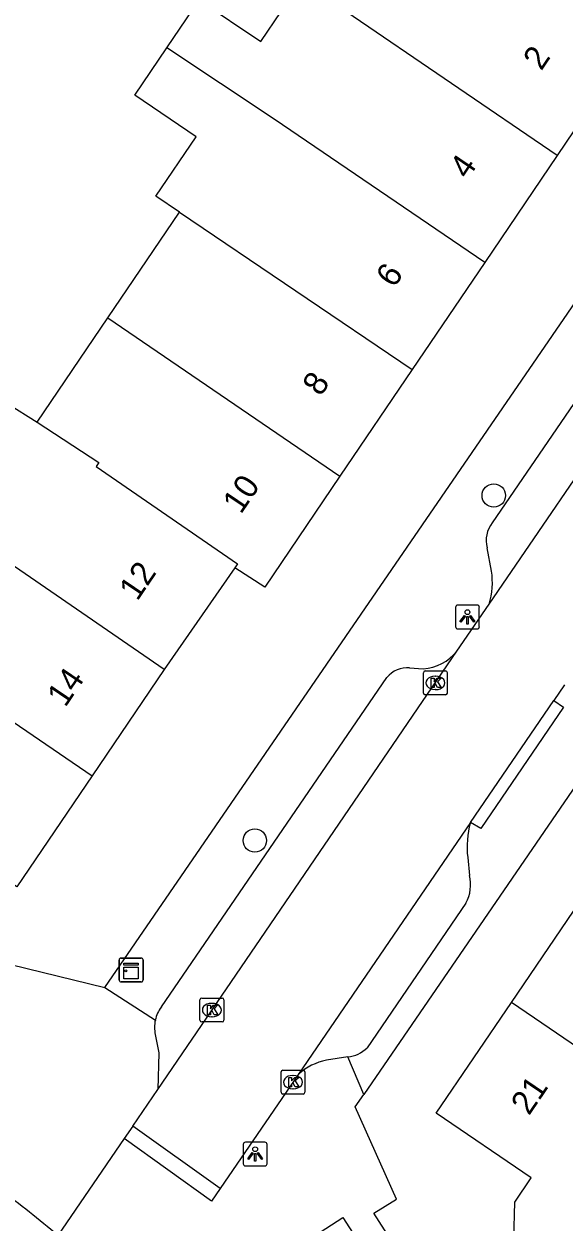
# Model space of a CAD drawing. Extents: x 157321 to 158827, y 386650 to 388532.
# Drawn here: x 157653.5 to 157676.1, y 387550 to 387600.2 of the extents above; entities that cross this region are included whole.
import ezdxf

# ---------------------------------------------------------------- set-up
doc = ezdxf.new("R2010")
doc.units = 0
for name, color, linetype in [('IMGEO_Boom', 7, 'Continuous'), ('IMGEO_Kast', 7, 'Continuous'), ('IMGEO_Kolk', 7, 'Continuous'), ('IMGEO_Lichtpunt', 7, 'Continuous'), ('IMGEO_Pand', 7, 'Continuous'), ('IMGEO_Pand_nummerreeks', 7, 'Continuous'), ('IMGEO_Rijbaan_lokaal_open', 7, 'Continuous'), ('IMGEO_Voetpad_open', 7, 'Continuous')]:
    doc.layers.add(name, color=color, linetype=linetype)

msp = doc.modelspace()

# ---------------------------------------------------------------- linework, layer by layer
at = {"layer": 'IMGEO_Boom'}
for centre in [(157673.185, 387580.433), (157663.191, 387565.995)]:
    msp.add_circle(centre, 0.489, dxfattribs=at)
at = {"layer": 'IMGEO_Kast'}
for p, q in [((157657.59, 387561.077), (157658.431, 387561.077)), ((157658.431, 387561.077), (157657.59, 387561.077)), ((157657.515, 387560.152), (157657.515, 387560.993)), ((157657.515, 387560.993), (157657.515, 387560.152)), ((157658.515, 387561.002), (157658.515, 387560.161)), ((157658.515, 387560.161), (157658.515, 387561.002)), ((157658.44, 387560.077), (157657.599, 387560.077)), ((157657.599, 387560.077), (157658.44, 387560.077))]:
    msp.add_line(p, q, dxfattribs=at)
for points in [[(157657.71, 387560.867), (157658.31, 387560.867), (157658.31, 387560.782), (157657.71, 387560.782), (157657.71, 387560.867)], [(157657.71, 387560.692), (157658.31, 387560.692), (157658.31, 387560.203), (157657.71, 387560.203), (157657.71, 387560.692)]]:
    msp.add_lwpolyline(points, dxfattribs=at)
msp.add_circle((157657.794, 387560.541), 0.0377, dxfattribs=at)
for centre, start, end in [((157657.593, 387560.999), 92.4484, 184.2845), ((157657.593, 387560.999), 92.4484, 184.2845), ((157658.437, 387560.999), 2.4484, 94.2845), ((157658.437, 387560.999), 2.4484, 94.2845), ((157657.593, 387560.155), 182.4484, 274.2845), ((157657.593, 387560.155), 182.4484, 274.2845), ((157658.437, 387560.155), 272.4484, 4.2845), ((157658.437, 387560.155), 272.4484, 4.2845)]:
    msp.add_arc(centre, 0.0779, start, end, dxfattribs=at)
at = {"layer": 'IMGEO_Kolk'}
for p, q in [((157670.317, 387573.092), (157671.169, 387573.092)), ((157670.242, 387572.166), (157670.242, 387573.018)), ((157670.73, 387572.872), (157670.755, 387572.872)), ((157671.243, 387573.018), (157671.243, 387572.166)), ((157671.169, 387572.092), (157670.317, 387572.092)), ((157670.753, 387572.312), (157670.728, 387572.312)), ((157660.894, 387558.477), (157660.894, 387559.329)), ((157660.969, 387559.403), (157661.821, 387559.403)), ((157661.382, 387559.183), (157661.407, 387559.183)), ((157661.895, 387559.329), (157661.895, 387558.477)), ((157661.405, 387558.623), (157661.38, 387558.623)), ((157661.821, 387558.403), (157660.969, 387558.403)), ((157664.287, 387555.459), (157664.287, 387556.311)), ((157664.362, 387556.385), (157665.214, 387556.385)), ((157664.775, 387556.165), (157664.8, 387556.165)), ((157665.288, 387556.311), (157665.288, 387555.459)), ((157664.798, 387555.605), (157664.773, 387555.605)), ((157665.214, 387555.385), (157664.362, 387555.385))]:
    msp.add_line(p, q, dxfattribs=at)
for points in [[(157670.317, 387573.092), (157671.169, 387573.092)], [(157670.242, 387572.166), (157670.242, 387573.018)], [(157670.563, 387572.792), (157670.686, 387572.792), (157670.686, 387572.641), (157670.816, 387572.792), (157670.98, 387572.792), (157670.834, 387572.641), (157670.987, 387572.392), (157670.835, 387572.392), (157670.75, 387572.556), (157670.686, 387572.489), (157670.686, 387572.392), (157670.563, 387572.392), (157670.563, 387572.792)], [(157671.243, 387573.018), (157671.243, 387572.166)], [(157671.169, 387572.092), (157670.317, 387572.092)], [(157660.894, 387558.477), (157660.894, 387559.329)], [(157660.969, 387559.403), (157661.821, 387559.403)], [(157661.215, 387559.103), (157661.338, 387559.103), (157661.338, 387558.952), (157661.468, 387559.103), (157661.632, 387559.103), (157661.486, 387558.952), (157661.639, 387558.703), (157661.487, 387558.703), (157661.402, 387558.867), (157661.338, 387558.8), (157661.338, 387558.703), (157661.215, 387558.703), (157661.215, 387559.103)], [(157661.895, 387559.329), (157661.895, 387558.477)], [(157661.821, 387558.403), (157660.969, 387558.403)], [(157664.287, 387555.459), (157664.287, 387556.311)], [(157664.362, 387556.385), (157665.214, 387556.385)], [(157664.608, 387556.085), (157664.731, 387556.085), (157664.731, 387555.934), (157664.861, 387556.085), (157665.025, 387556.085), (157664.879, 387555.934), (157665.032, 387555.685), (157664.88, 387555.685), (157664.795, 387555.849), (157664.731, 387555.782), (157664.731, 387555.685), (157664.608, 387555.685), (157664.608, 387556.085)], [(157665.288, 387556.311), (157665.288, 387555.459)], [(157665.214, 387555.385), (157664.362, 387555.385)]]:
    msp.add_lwpolyline(points, dxfattribs=at)
for centre, start, end in [((157670.319, 387573.016), 91.552, 178.448), ((157670.319, 387573.016), 91.552, 178.448), ((157671.167, 387573.016), 1.552, 88.448), ((157671.167, 387573.016), 1.552, 88.448), ((157670.319, 387572.168), 181.552, 268.448), ((157670.319, 387572.168), 181.552, 268.448), ((157671.167, 387572.168), 271.552, 358.448), ((157671.167, 387572.168), 271.552, 358.448), ((157660.971, 387559.327), 91.552, 178.448), ((157660.971, 387559.327), 91.552, 178.448), ((157661.819, 387559.327), 1.552, 88.448), ((157661.819, 387559.327), 1.552, 88.448), ((157660.971, 387558.479), 181.552, 268.448), ((157660.971, 387558.479), 181.552, 268.448), ((157661.819, 387558.479), 271.552, 358.448), ((157661.819, 387558.479), 271.552, 358.448), ((157664.364, 387556.309), 91.552, 178.448), ((157664.364, 387556.309), 91.552, 178.448), ((157665.212, 387556.309), 1.552, 88.448), ((157665.212, 387556.309), 1.552, 88.448), ((157664.364, 387555.461), 181.552, 268.448), ((157664.364, 387555.461), 181.552, 268.448), ((157665.212, 387555.461), 271.552, 358.448), ((157665.212, 387555.461), 271.552, 358.448)]:
    msp.add_arc(centre, 0.0765, start, end, dxfattribs=at)
for centre, major_axis, ratio, start_param, end_param in [((157670.729, 387572.592), (-0.387, 0.002), 0.722429, 4.712389, 7.853982), ((157670.754, 387572.592), (-0.39, 0.002), 0.717154, 1.570796, 4.712389), ((157661.381, 387558.903), (-0.387, 0.002), 0.722429, 4.712389, 7.853982), ((157661.406, 387558.903), (-0.39, 0.002), 0.717154, 1.570796, 4.712389), ((157664.774, 387555.885), (-0.387, 0.002), 0.722429, 4.712389, 7.853982), ((157664.799, 387555.885), (-0.39, 0.002), 0.717154, 1.570796, 4.712389)]:
    msp.add_ellipse(centre, major_axis=major_axis, ratio=ratio, start_param=start_param, end_param=end_param, dxfattribs=at)
at = {"layer": 'IMGEO_Lichtpunt'}
for p, q in [((157671.586, 387575.753), (157671.586, 387574.946)), ((157671.586, 387575.753), (157671.586, 387574.946)), ((157672.488, 387575.848), (157671.68, 387575.848)), ((157672.488, 387575.848), (157671.68, 387575.848)), ((157672.582, 387574.946), (157672.582, 387575.753)), ((157672.582, 387574.946), (157672.582, 387575.753)), ((157671.68, 387574.852), (157672.488, 387574.852)), ((157671.68, 387574.852), (157672.488, 387574.852)), ((157662.705, 387553.279), (157662.705, 387552.472)), ((157662.705, 387553.279), (157662.705, 387552.472)), ((157663.607, 387553.374), (157662.799, 387553.374)), ((157663.607, 387553.374), (157662.799, 387553.374)), ((157663.701, 387552.472), (157663.701, 387553.279)), ((157663.701, 387552.472), (157663.701, 387553.279)), ((157662.799, 387552.378), (157663.607, 387552.378)), ((157662.799, 387552.378), (157663.607, 387552.378))]:
    msp.add_line(p, q, dxfattribs=at)
for points in [[(157671.96, 387575.417), (157671.999, 387575.389), (157671.811, 387575.127), (157671.773, 387575.154), (157671.96, 387575.417)], [(157672.062, 387575.369), (157672.109, 387575.369), (157672.109, 387575.047), (157672.062, 387575.047), (157672.062, 387575.369)], [(157672.172, 387575.389), (157672.21, 387575.416), (157672.397, 387575.154), (157672.358, 387575.126), (157672.172, 387575.389)], [(157663.079, 387552.943), (157663.118, 387552.915), (157662.93, 387552.653), (157662.892, 387552.68), (157663.079, 387552.943)], [(157663.181, 387552.895), (157663.228, 387552.895), (157663.228, 387552.573), (157663.181, 387552.573), (157663.181, 387552.895)], [(157663.291, 387552.915), (157663.329, 387552.942), (157663.516, 387552.68), (157663.477, 387552.652), (157663.291, 387552.915)]]:
    msp.add_lwpolyline(points, dxfattribs=at)
for centre in [(157672.085, 387575.551), (157663.204, 387553.077)]:
    msp.add_circle(centre, 0.0994, dxfattribs=at)
for centre, start, end in [((157671.68, 387575.753), 90, 180), ((157671.68, 387575.753), 90, 180), ((157672.488, 387575.753), 0, 90), ((157672.488, 387575.753), 0, 90), ((157671.68, 387574.946), 180, 270), ((157671.68, 387574.946), 180, 270), ((157672.488, 387574.946), 270, 0), ((157672.488, 387574.946), 270, 360), ((157662.799, 387553.279), 90, 180), ((157662.799, 387553.279), 90, 180), ((157663.607, 387553.279), 0, 90), ((157663.607, 387553.279), 0, 90), ((157662.799, 387552.472), 180, 270), ((157662.799, 387552.472), 180, 270), ((157663.607, 387552.472), 270, 0), ((157663.607, 387552.472), 270, 360)]:
    msp.add_arc(centre, 0.0946, start, end, dxfattribs=at)
at = {"layer": 'IMGEO_Pand'}
for points in [[(157666.998, 387600.692), (157667.045, 387600.761), (157674.312, 387611.492), (157676.06, 387610.308), (157680.199, 387607.505), (157677.721, 387603.845), (157675.982, 387601.278), (157678.954, 387599.264), (157675.839, 387594.663)], [(157659.511, 387599.161), (157660.868, 387601.165), (157663.435, 387599.426), (157665.147, 387601.954), (157666.998, 387600.692)], [(157675.839, 387594.663), (157666.998, 387600.692)], [(157660.032, 387592.292), (157659.052, 387592.955), (157660.737, 387595.444), (157658.171, 387597.182), (157659.511, 387599.161)], [(157672.806, 387590.185), (157664.003, 387596.179), (157659.511, 387599.161)], [(157675.839, 387594.663), (157672.806, 387590.185)], [(157657.039, 387587.871), (157660.032, 387592.292)], [(157660.032, 387592.292), (157669.773, 387585.706)], [(157672.806, 387590.185), (157669.773, 387585.706)], [(157654.085, 387583.507), (157657.039, 387587.871)], [(157657.039, 387587.871), (157666.751, 387581.243)], [(157669.773, 387585.706), (157666.751, 387581.243)], [(157649.77, 387579.754), (157652.839, 387584.289), (157654.085, 387583.507)], [(157654.085, 387583.507), (157656.66, 387581.81), (157656.549, 387581.645), (157662.472, 387577.574), (157662.36, 387577.41)], [(157666.751, 387581.243), (157663.608, 387576.602), (157662.36, 387577.41)], [(157659.401, 387573.157), (157652.267, 387578.041), (157649.77, 387579.754)], [(157662.36, 387577.41), (157659.401, 387573.157)], [(157656.385, 387568.704), (157653.237, 387564.056), (157648.989, 387566.932), (157647.746, 387565.095), (157642.33, 387568.761), (157645.133, 387572.902), (157646.781, 387575.338)], [(157646.781, 387575.338), (157649.232, 387573.579), (157656.385, 387568.704)], [(157659.401, 387573.157), (157656.385, 387568.704)], [(157673.928, 387559.222), (157677.05, 387563.822), (157679.759, 387561.983), (157681.403, 387564.406)], [(157681.146, 387554.299), (157678.007, 387549.675), (157677.286, 387550.164), (157676.592, 387549.142), (157675.192, 387548.511), (157674.024, 387549.304), (157674.061, 387550.86), (157674.755, 387551.882), (157670.778, 387554.58), (157673.928, 387559.222)], [(157681.146, 387554.299), (157673.928, 387559.222)]]:
    msp.add_lwpolyline(points, dxfattribs=at)
at = {"layer": 'IMGEO_Rijbaan_lokaal_open'}
for points in [[(157672.994, 387575.888), (157678.803, 387584.395), (157685.555, 387594.174)], [(157671.645, 387573.913), (157672.994, 387575.888)], [(157659.127, 387555.582), (157671.645, 387573.913)], [(157676.142, 387572.505), (157675.697, 387571.853)], [(157672.207, 387566.745), (157675.697, 387571.853)], [(157672.207, 387566.745), (157665.014, 387556.216)], [(157665.014, 387556.216), (157661.745, 387551.433)], [(157658.08, 387554.049), (157659.127, 387555.582)], [(157658.08, 387554.049), (157657.719, 387553.52)], [(157661.745, 387551.433), (157658.08, 387554.049)], [(157661.745, 387551.433), (157661.384, 387550.904), (157657.719, 387553.52)]]:
    msp.add_lwpolyline(points, dxfattribs=at)
at = {"layer": 'IMGEO_Voetpad_open'}
for points in [[(157712.78, 387615.384), (157707.158, 387612.356), (157706.257, 387611.54), (157692.204, 387591.043), (157667.746, 387555.368)], [(157656.917, 387559.848), (157687.645, 387604.627)], [(157673.126, 387579.286), (157682.483, 387592.951)], [(157673.089, 387577.268), (157672.911, 387578.245)], [(157669.665, 387573.216), (157670.236, 387573.178)], [(157659.28, 387559.03), (157668.713, 387572.822)], [(157675.697, 387571.853), (157676.109, 387571.571), (157672.641, 387566.495), (157672.207, 387566.745)], [(157633.936, 387565.471), (157656.917, 387559.848)], [(157672.095, 387565.284), (157672.172, 387564.536)], [(157672.021, 387563.38), (157667.887, 387557.323)], [(157656.917, 387559.848), (157659.028, 387558.48)], [(157659.027, 387557.875), (157659.18, 387557.113), (157659.127, 387555.582)], [(157667.075, 387556.941), (157666.187, 387556.801)], [(157667.746, 387555.368), (157667.075, 387556.941)], [(157667.475, 387536.826), (157674.116, 387541.126), (157668.171, 387550.405), (157669.123, 387550.99), (157667.388, 387554.848), (157667.746, 387555.368)], [(157657.719, 387553.52), (157654.952, 387549.465)], [(157666.877, 387550.226), (157670.956, 387543.882), (157666.605, 387541.061), (157662.563, 387547.43), (157666.877, 387550.226)]]:
    msp.add_lwpolyline(points, dxfattribs=at)
for centre, radius, start, end in [((157674.008, 387578.561), 1.142, 140.5967, 196.0646), ((157670.126, 387576.779), 3.003, 342.7479, 9.3759), ((157670.075, 387575.205), 2.033, 274.5452, 320.552), ((157669.569, 387572.1), 1.12, 85.0919, 139.8741), ((157676.098, 387565.712), 4.026, 165.1312, 186.1014), ((157670.625, 387564.15), 1.594, 331.1107, 14.0052), ((157660.395, 387558.186), 1.399, 142.8923, 167.875), ((157660.419, 387558.175), 1.424, 167.6405, 192.17), ((157666.96, 387558.24), 1.304, 275.0683, 315.3204), ((157666.644, 387554.416), 2.428, 100.8488, 132.164), ((157618.917, 387506.752), 55.884, 49.8472, 53.0183)]:
    msp.add_arc(centre, radius, start, end, dxfattribs=at)

# ---------------------------------------------------------------- texts
at = {"layer": 'IMGEO_Pand_nummerreeks'}
for s, rotation, p in [('2', 55.8978, (157675.173, 387598.175)), ('4', 55.8978, (157672.096, 387593.631)), ('6', 55.8978, (157669.018, 387589.086)), ('8', 55.8978, (157665.942, 387584.544)), ('10', 55.8954, (157662.606, 387579.617)), ('12', 55.8921, (157658.272, 387575.984)), ('14', 55.8921, (157655.26, 387571.536)), ('21', 55.8376, (157674.66, 387554.458))]:
    msp.add_text(s, height=1, rotation=rotation, dxfattribs=at).set_placement(p)

doc.saveas('drawing.dxf')
